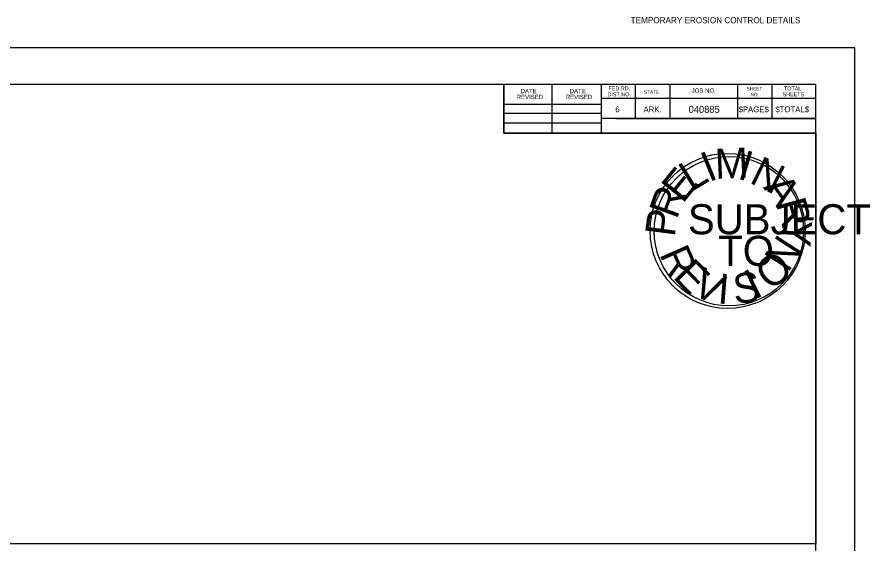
# Model space of a CAD drawing. Extents: x -1.6 to 32.7, y -1.7 to 21.9.
# Drawn here: x 15.57 to 32.71, y 11.31 to 21.89 of the extents above; entities that cross this region are included whole.
import ezdxf

# ---------------------------------------------------------------- set-up
doc = ezdxf.new("R2010")
doc.units = 0
for name, color, linetype in [('Level 1', 7, 'Continuous'), ('Level 62', 7, 'Continuous'), ('Level 63', 7, 'Continuous'), ('R_Border', 7, 'Continuous'), ('R_Border Prelim', 7, 'Continuous'), ('R_Border_Dark', 7, 'Continuous'), ('Stamp Mask', 7, 'Continuous'), ('TYPICAL FONT', 7, 'Continuous')]:
    doc.layers.add(name, color=color, linetype=linetype)

msp = doc.modelspace()

# ---------------------------------------------------------------- linework, layer by layer
at = {"layer": 'Level 1'}
for p, q in [((-0.001, 20.545), (31.617, 20.545)), ((25.353, 19.557), (25.353, 20.545)), ((26.321, 19.557), (26.321, 20.525)), ((27.307, 20.545), (27.307, 19.557)), ((27.991, 20.545), (27.991, 19.851)), ((28.685, 20.545), (28.685, 19.851)), ((30.043, 20.545), (30.043, 19.851)), ((30.737, 20.545), (30.737, 19.851)), ((31.617, -0.001), (31.617, 20.545)), ((31.617, 20.251), (27.307, 20.251)), ((31.617, 20.253), (31.617, 20.253)), ((25.353, 20.143), (27.307, 20.143)), ((25.353, 19.957), (27.307, 19.957)), ((25.353, 19.763), (27.307, 19.763)), ((31.617, 19.851), (27.307, 19.851)), ((27.603, 19.851), (31.617, 19.851)), ((31.617, 19.557), (25.353, 19.557))]:
    msp.add_line(p, q, dxfattribs=at)
msp.add_lwpolyline([(-0.001, 20.545), (25.353, 20.545), (25.353, 19.557), (27.307, 19.557), (27.307, 19.557), (31.617, 19.557), (31.617, 11.307), (-0.001, 11.307)], close=True, dxfattribs=at)
at = {"layer": 'Level 62'}
msp.add_lwpolyline([(-0.001, 20.545), (25.353, 20.545), (25.353, 20.545), (25.353, 19.557), (25.353, 19.557), (26.987, 19.557), (27.307, 19.557), (27.307, 19.557), (27.307, 19.557), (31.617, 19.557), (31.617, 11.307), (-0.001, 11.307)], close=True, dxfattribs=at)
at = {"layer": 'Level 63'}
msp.add_lwpolyline([(-1.598, -0.727), (32.402, -0.727), (32.402, 21.273), (-1.598, 21.273)], close=True, dxfattribs=at)
at = {"layer": 'R_Border Prelim'}
msp.add_circle((29.874, 17.589), 1.5, dxfattribs=at)
at = {"layer": 'R_Border_Dark'}
msp.add_line((31.617, 11.307), (-0.001, 11.307), dxfattribs=at)
at = {"layer": 'Stamp Mask'}
msp.add_circle((29.847, 17.594), 1.557, dxfattribs=at)

# ---------------------------------------------------------------- texts
at = {"layer": 'Level 1'}
for s, height, p in [('DATE', 0.0879, (25.687, 20.359)), ('DATE', 0.0879, (26.673, 20.359)), ('FED.RD.', 0.0782, (27.455, 20.417)), ('STATE', 0.0684, (28.167, 20.349)), ('SHEET', 0.0684, (30.229, 20.417)), ('TOTAL', 0.0782, (30.981, 20.417)), ('REVISED', 0.0879, (25.609, 20.241)), ('REVISED', 0.0879, (26.595, 20.241)), ('DIST.NO.', 0.0782, (27.435, 20.299)), ('NO.', 0.0684, (30.307, 20.299)), ('SHEETS', 0.0782, (30.953, 20.299)), ('6', 0.117, (27.591, 19.977)), ('ARK.', 0.1172, (28.157, 19.977)), ('040885', 0.14, (29.064, 19.966)), ('$PAGE$', 0.1172, (30.067, 19.977)), ('$TOTAL$', 0.1172, (30.806, 19.977))]:
    msp.add_text(s, height=height, dxfattribs=at).set_placement(p)
at = {"layer": 'R_Border'}
msp.add_text('JOB NO.', height=0.0879, dxfattribs=at).set_placement((29.125, 20.369))
msp.add_text('JOB NO.', height=0.0879, dxfattribs=at).set_placement((29.125, 20.369))
at = {"layer": 'R_Border Prelim'}
for s, rotation, p in [('M', 2.6943, (29.605, 18.637)), ('I', 343.3781, (30.027, 18.649)), ('I', 22.0105, (29.472, 18.571)), ('N', 333.7199, (30.266, 18.572)), ('E', 50.9849, (28.944, 18.13)), ('L', 31.6686, (29.122, 18.373)), ('A', 304.7456, (30.549, 18.468)), ('R', 70.3011, (28.824, 17.812)), ('R', 285.4294, (30.812, 18.162)), ('P', 82.6089, (28.784, 17.46)), ('Y', 266.1131, (30.947, 17.836)), ('N', 57.1378, (31.062, 16.738)), ('R', 293.7639, (28.471, 17.13)), ('E', 314.3262, (28.73, 16.659)), ('O', 36.5754, (30.697, 16.38)), ('V', 334.8885, (29.104, 16.332)), ('I', 26.2943, (30.389, 16.211)), ('I', 355.4508, (29.635, 16.139)), ('S', 5.732, (29.985, 16.128))]:
    msp.add_text(s, height=0.603, rotation=rotation, dxfattribs=at).set_placement(p)
for s, p in [('SUBJECT', (29.05, 17.527)), ('TO', (29.659, 16.893))]:
    msp.add_text(s, height=0.6034, dxfattribs=at).set_placement(p)
at = {"layer": 'TYPICAL FONT'}
msp.add_text('TEMPORARY EROSION CONTROL DETAILS', height=0.1224, dxfattribs=at).set_placement((27.9, 21.766))

doc.saveas('drawing.dxf')
